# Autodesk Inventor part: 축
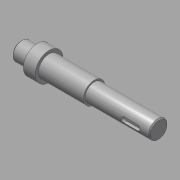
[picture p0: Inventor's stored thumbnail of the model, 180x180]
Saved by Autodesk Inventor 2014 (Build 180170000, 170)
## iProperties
Created: 2015-09
Part Number: 축
Material: 강철, 연강
Document SubType Name: Modeling
Designer: mduedu
Density: 7.86 g/cm^3
Mass: 263.424 g
Surface Area: 86.4309 cm^2
Volume: 33.5145 cm^3
Appearance: 강철
Author: mduedu
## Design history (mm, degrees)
sketch "스케치1"
  geometry: L1 (-69, 0)-(69, 0); L2 (-69, 0)-(-69, 8.5); L3 (-69, 8.5)-(-54, 8.5); L4 (-54, 8.5)-(-54, 13); L5 (-54, 13)-(-43, 13); L6 (-43, 13)-(-43, 10); L7 (-43, 10)-(-1, 10); L8 (-1, 10)-(-1, 8.5); L9 (-1, 8.5)-(69, 8.5); L10 (69, 8.5)-(69, 0); 2 further points
  constraints: 20 end point, 5 parallel, 2 horizontal, 2 perpendicular, 1 coincident, 1 midpoint, 1 vertical
  dimensions: "d0" = 138 distance of L1.start L1.end; "d2" = 11 distance of L4.end L5.end; "d3" = 42 distance of L6.end L7.end; "d4" = 70 distance of L8.end L9.end; "d5" = 17 diameter of L3 L1; "d6" = 17 diameter of L9 L1; "d7" = 20 diameter of L7 L1; "d8" = 26 diameter of L5 L1
revolve "회전1" sketch "스케치1" stored, may be unused: angle "d9" = 90 deg
node "작업 평면1"
sketch "스케치2"
  geometry: L1 (10.5, 2.5)-(23.5, 2.5); L2 (23.5, -2.5)-(10.5, -2.5); L3 (10.5, 2.5)-(23.5, -2.5); L4 (23.5, 2.5)-(10.5, -2.5); L5 (35, -8.5)-(35, 8.5) reference; A1 r 2.5 centre (10.5, 0) between (10.5, 2.5) and (10.5, -2.5); A2 r 2.5 centre (23.5, 0) between (23.5, -2.5) and (23.5, 2.5); 2 further points
  constraints: 8 end point, 4 point on circle, 4 tangent, 2 centre point, 2 midpoint, 1 horizontal, 1 horizontal alignment, 1 parallel
  dimensions: "d10" = 18 dimension on A2 A1; "d12" = 9 distance edge to line of A2 L5; "d13" = 5 distance between parallel lines of L2 L1
extrude "돌출1" cut sketch "스케치2" distance "d14" = 3; taper "d15" = 0 deg
node "작업 평면2"
sketch "스케치4"
  geometry: L1 (7, -3)-(-9, -3); L2 (-9, 3)-(7, 3); L3 (-21, 10)-(-21, -10) reference; A1 r 3 centre (-9, 0) between (-9, 3) and (-9, -3); A2 r 3 centre (7, 0) between (7, -3) and (7, 3); 1 further point
  constraints: 4 end point, 4 point on circle, 4 tangent, 2 centre point, 1 horizontal, 1 horizontal alignment, 1 parallel
  dimensions: "d16" = 22 dimension on A1 A2; "d18" = 6 distance between parallel lines of L2 L1; "d19" = 9 distance edge to line of A1 L3
extrude "돌출2" cut sketch "스케치4" distance "d20" = 3.5; taper "d21" = 0 deg
sketch "스케치5"
  geometry: L1 (-1, 8.5)-(69, 8.5) reference; L2 (-1, -8.5)-(69, -8.5) reference; L3 (42, 8.5)-(42, -8.5); L4 (42, -6.5)-(40, -8.5); L5 (42, -8.5)-(40, -8.5); L6 (42, -8.5)-(42, -6.5); L7 (-1, -10)-(-1, 10) reference; 1 further point
  constraints: 8 end point, 4 point on line, 1 collinear, 1 perpendicular
  dimensions: "d22" = 4 diameter of L4.end L3; "d24" = 45 deg angle of L3 L4; "d26" = 43 distance between parallel lines of L3 L7
revolve "회전2" sketch "스케치5" stored, may be unused: angle "d27" = 90 deg
chamfer "모따기1" distance "d28" = 1; stored, may be unused: second distance "d29" = 2, angle "d30" = 45 deg
sketch "스케치6"
  geometry: L1 (42, -6.5)-(40, -8.5) reference; L2 (42, -6.5)-(44, -8.5) reference; 2 further points
  constraints: 1 coincident
node "솔리드1"
